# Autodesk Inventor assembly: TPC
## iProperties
Shininess: 64.0
Length Units: 11272
Angle Units: 11279
Time Units: 11290
Mass Units: 11286
Length Display Precision: 3
Angle Display Precision: 2
Compacted: True
Part Number: TPC
Document SubType Name: Assembly
Created: 2004-08
Designer: Lori
Manufacturer: Standard
Standards Organization: Custom
Density: 0.0
Volumn: 0.0
Area: 0.0
PropertySet Name: Model Information
Control State: 0
Master: False
Checked Out: False
Author: Lori
